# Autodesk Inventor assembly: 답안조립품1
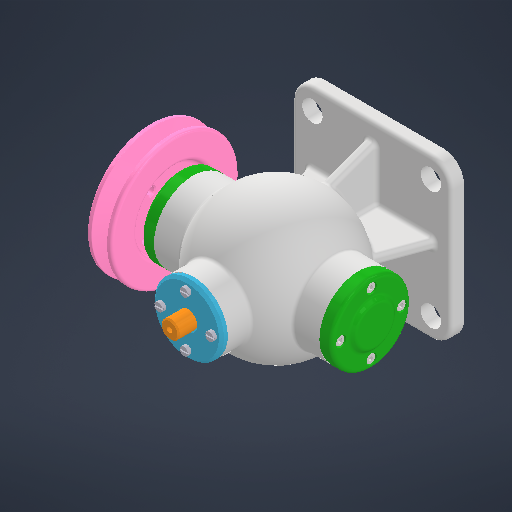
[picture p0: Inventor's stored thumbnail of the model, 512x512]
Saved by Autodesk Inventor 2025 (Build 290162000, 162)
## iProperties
Created: 2025-08
Part Number: 답안조립품1
Document SubType Name: Assembly
Designer: infra11
Author: infra11
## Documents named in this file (15)
- C:\Users\infra11\Desktop\동고비\답안조립품1.iam
- C:\Users\infra11\Desktop\동고비\본체.ipt
- C:\Users\infra11\Desktop\동고비\V-벨트풀리\V-벨트풀리.ipt
- C:\Users\infra11\Desktop\동고비\너트 M8\너트 M8.ipt
- C:\Users\infra11\Desktop\동고비\뒤커버\뒤커버.ipt
- C:\Users\infra11\Desktop\동고비\베어링- 6202\베어링- 6202.ipt
- C:\Users\infra11\Desktop\동고비\볼트 M4 x 12\볼트 M4 x 12.ipt
- C:\Users\infra11\Desktop\동고비\볼트 M4 x 16\볼트 M4 x 16.ipt
- C:\Users\infra11\Desktop\동고비\상부커버\상부커버.ipt
- C:\Users\infra11\Desktop\동고비\슬라이드\슬라이드.ipt
- C:\Users\infra11\Desktop\동고비\앞커버\앞커버.ipt
- C:\Users\infra11\Desktop\동고비\오일실 15 30 7\오일실 15 30 7.ipt
- C:\Users\infra11\Desktop\동고비\칼라\칼라.ipt
- C:\Users\infra11\Desktop\동고비\키 4 x 4 x 12\키 4 x 4 x 12.ipt
- C:\Users\infra11\Desktop\동고비\편심축\편심축.ipt
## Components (1 placed, 1 different names)
1. V-벨트풀리:1
